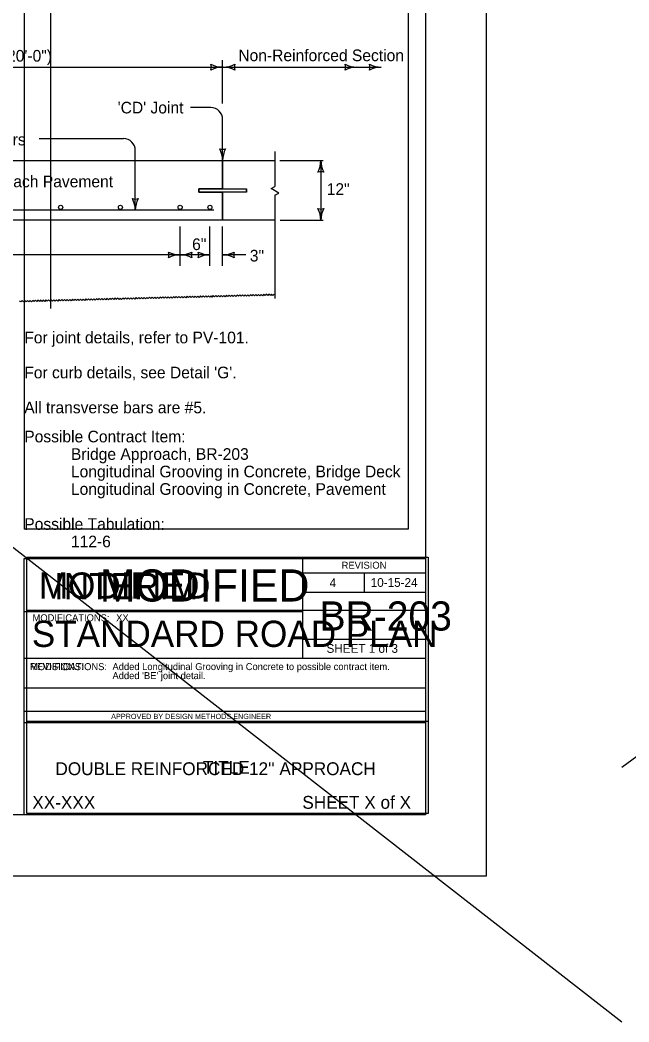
# Model space of a CAD drawing. Extents: x 8925 to 81668, y 4369 to 11918.
# Drawn here: x 12543 to 13587, y 4369 to 6087 of the extents above; entities that cross this region are included whole.
import ezdxf

# ---------------------------------------------------------------- set-up
doc = ezdxf.new("R2010")
doc.units = 0
for name, color, linetype in [('dsnCellElements', 7, 'Continuous'), ('dsnNonPlotable', 7, 'Continuous'), ('dsnShtPlotShapeBatchPrint', 7, 'Continuous'), ('dsnStdBlock', 7, 'Continuous'), ('dsnstdblockInterim', 7, 'Continuous'), ('dsnStdBlockModified', 7, 'Continuous'), ('dsnStdBlockNotModified', 7, 'Continuous'), ('dsnStdBorder', 7, 'Continuous'), ('dsnStdLabel', 7, 'Continuous'), ('dsnstdModifiedBlock', 7, 'Continuous'), ('Level 1', 7, 'Continuous'), ('Level 2', 7, 'Continuous'), ('Level 3', 7, 'Continuous'), ('SheetBorder', 7, 'Continuous')]:
    doc.layers.add(name, color=color, linetype=linetype)

msp = doc.modelspace()

# ---------------------------------------------------------------- linework, layer by layer
at = {"layer": 'dsnShtPlotShapeBatchPrint'}
for p, q in [((12890.1, 5943.6), (12890.1, 6018.3)), ((11921.5, 6006.2), (12890.1, 6006.2)), ((12890.1, 6006.1), (13161.7, 6006.1)), ((12869.9, 5936.8), (12835, 5936.8)), ((12890.1, 5846), (12890.1, 5916.6)), ((12575.6, 5883.6), (12720.2, 5883.6)), ((12740.4, 5760.8), (12740.4, 5863.4)), ((12433.4, 5846), (12890.1, 5846)), ((12433.4, 5846), (12890.1, 5846)), ((12890.1, 5846), (12890.1, 5797.7)), ((12890.1, 5846), (12979.6, 5846)), ((12988.4, 5845.9), (13062.2, 5845.9)), ((13058.4, 5845.9), (13058.4, 5743.6)), ((12890.1, 5797.7), (12849.2, 5797.7)), ((12849.2, 5797.7), (12849.2, 5792)), ((12849.2, 5797.7), (12849.2, 5792)), ((12849.2, 5792), (12890.1, 5792)), ((12890.1, 5792), (12890.1, 5743.7)), ((12931, 5792), (12931, 5797.7)), ((12890.1, 5743.7), (12433.4, 5743.7)), ((12890.1, 5743.7), (12433.4, 5743.7)), ((12979.6, 5743.7), (12890.1, 5743.7)), ((12988.9, 5743.6), (13062.2, 5743.6)), ((12817.2, 5665.2), (12817.2, 5733.2)), ((12868.3, 5665.2), (12868.3, 5733.2)), ((12890.1, 5665.2), (12890.1, 5733.2)), ((12817.2, 5684.2), (11994.4, 5684.2)), ((12868.3, 5684.2), (12817.2, 5684.2)), ((12929.9, 5684.2), (12890.1, 5684.2))]:
    msp.add_line(p, q, dxfattribs=at)
for points in [[(12542.9, 5604.6), (12541.8, 5605.7)], [(12597.6, 5606), (12596.4, 5607.1), (12594.2, 5604.8), (12591.8, 5607), (12589.6, 5604.7), (12587.3, 5606.9), (12585.1, 5604.5), (12582.7, 5606.8), (12580.5, 5604.4), (12578.2, 5606.6), (12576, 5604.3), (12573.6, 5606.5), (12571.4, 5604.2), (12569.1, 5606.4), (12566.9, 5604.1), (12564.5, 5606.3), (12562.3, 5604), (12560, 5606.2), (12557.8, 5603.8), (12555.4, 5606), (12553.2, 5603.7), (12550.9, 5605.9), (12548.7, 5603.6), (12546.3, 5605.8), (12544.1, 5603.5), (12542.9, 5604.6)], [(12652.2, 5607.4), (12651, 5608.5), (12648.8, 5606.2), (12646.4, 5608.4), (12644.2, 5606.1), (12641.9, 5608.3), (12639.7, 5606), (12637.3, 5608.2), (12635.1, 5605.9), (12632.8, 5608.1), (12630.6, 5605.7), (12628.2, 5607.9), (12626, 5605.6), (12623.7, 5607.8), (12621.5, 5605.5), (12619.1, 5607.7), (12616.9, 5605.4), (12614.6, 5607.6), (12612.4, 5605.3), (12610, 5607.5), (12607.8, 5605.1), (12605.5, 5607.3), (12603.3, 5605), (12600.9, 5607.2), (12598.7, 5604.9), (12597.6, 5606)], [(12706.8, 5608.9), (12705.6, 5610), (12703.4, 5607.6), (12701.1, 5609.8), (12698.8, 5607.5), (12696.5, 5609.7), (12694.3, 5607.4), (12691.9, 5609.6), (12689.7, 5607.3), (12687.4, 5609.5), (12685.2, 5607.2), (12682.9, 5609.4), (12680.6, 5607), (12678.3, 5609.3), (12676.1, 5606.9), (12673.8, 5609.1), (12671.5, 5606.8), (12669.2, 5609), (12667, 5606.7), (12664.6, 5608.9), (12662.4, 5606.6), (12660.1, 5608.8), (12657.9, 5606.4), (12655.5, 5608.7), (12653.3, 5606.3), (12652.2, 5607.4)], [(12761.4, 5610.3), (12760.2, 5611.4), (12758, 5609.1), (12755.7, 5611.3), (12753.4, 5608.9), (12751.1, 5611.2), (12748.9, 5608.8), (12746.6, 5611), (12744.3, 5608.7), (12742, 5610.9), (12739.8, 5608.6), (12737.5, 5610.8), (12735.2, 5608.5), (12732.9, 5610.7), (12730.7, 5608.3), (12728.4, 5610.6), (12726.1, 5608.2), (12723.8, 5610.4), (12721.6, 5608.1), (12719.3, 5610.3), (12717, 5608), (12714.7, 5610.2), (12712.5, 5607.9), (12710.2, 5610.1), (12707.9, 5607.8), (12706.8, 5608.9)], [(12816, 5611.7), (12814.8, 5612.8), (12812.6, 5610.5), (12810.3, 5612.7), (12808, 5610.4), (12805.7, 5612.6), (12803.5, 5610.3), (12801.2, 5612.5), (12798.9, 5610.1), (12796.6, 5612.3), (12794.4, 5610), (12792.1, 5612.2), (12789.9, 5609.9), (12787.5, 5612.1), (12785.3, 5609.8), (12783, 5612), (12780.7, 5609.7), (12778.4, 5611.9), (12776.2, 5609.5), (12773.9, 5611.7), (12771.6, 5609.4), (12769.3, 5611.6), (12767.1, 5609.3), (12764.8, 5611.5), (12762.5, 5609.2), (12761.4, 5610.3)], [(12871.6, 5613.1), (12870.4, 5614.2), (12868.2, 5611.9), (12865.8, 5614.1), (12863.6, 5611.8), (12861.3, 5614), (12859.1, 5611.7), (12856.7, 5613.9), (12854.5, 5611.6), (12852.2, 5613.8), (12850, 5611.4), (12847.6, 5613.7), (12845.4, 5611.3), (12843.1, 5613.5), (12840.9, 5611.2), (12838.5, 5613.4), (12836.3, 5611.1), (12834, 5613.3), (12831.8, 5611), (12829.4, 5613.2), (12827.2, 5610.8), (12824.9, 5613.1), (12822.7, 5610.7), (12820.3, 5612.9), (12818.1, 5610.6), (12816.9, 5611.7)], [(12925.2, 5614.6), (12924, 5615.7), (12921.8, 5613.3), (12919.5, 5615.6), (12917.3, 5613.2), (12914.9, 5615.4), (12912.7, 5613.1), (12910.4, 5615.3), (12908.2, 5613), (12905.8, 5615.2), (12903.6, 5612.9), (12901.3, 5615.1), (12899.1, 5612.7), (12896.7, 5615), (12894.5, 5612.6), (12892.2, 5614.8), (12890, 5612.5), (12887.6, 5614.7), (12885.4, 5612.4), (12883.1, 5614.6), (12880.9, 5612.3), (12878.5, 5614.5), (12876.3, 5612.2), (12874, 5614.4), (12871.8, 5612), (12870.6, 5613.1)], [(12979.8, 5616), (12978.6, 5617.1), (12976.4, 5614.8), (12974.1, 5617), (12971.9, 5614.6), (12969.5, 5616.9), (12967.3, 5614.5), (12965, 5616.7), (12962.8, 5614.4), (12960.4, 5616.6), (12958.2, 5614.3), (12955.9, 5616.5), (12953.7, 5614.2), (12951.3, 5616.4), (12949.1, 5614), (12946.8, 5616.3), (12944.6, 5613.9), (12942.2, 5616.1), (12940, 5613.8), (12937.7, 5616), (12935.5, 5613.7), (12933.1, 5615.9), (12930.9, 5613.6), (12928.6, 5615.8), (12926.4, 5613.5), (12925.2, 5614.6)]]:
    msp.add_lwpolyline(points, dxfattribs=at)
for centre in [(12869.9, 5916.6), (12720.2, 5863.4)]:
    msp.add_arc(centre, 20.2, 0, 90, dxfattribs=at)
at = {"layer": 'dsnStdBlock'}
msp.add_lwpolyline([(10103, 6733.9), (13238, 6733.9), (13238, 4723.9), (10103, 4723.9)], close=True, dxfattribs=at)
at = {"layer": 'dsnStdBlockModified'}
for p, q in [((12550, 6683.9), (12550, 5213.9)), ((13208, 6683.9), (13208, 5213.9)), ((12595, 6583.9), (12595, 5592.4)), ((13208, 5213.9), (12550, 5213.9))]:
    msp.add_line(p, q, dxfattribs=at)
at = {"layer": 'dsnStdBlockNotModified'}
msp.add_lwpolyline([(9998.5, 4619.4), (13342.5, 4619.4), (13342.5, 7203.4), (9998.5, 7203.4)], close=True, dxfattribs=at)
at = {"layer": 'dsnStdBorder'}
for p, q in [((12979.6, 5861.7), (12979.6, 5801.6)), ((12890.1, 5797.7), (12890.1, 5846)), ((12849.2, 5792), (12849.2, 5797.7)), ((12849.2, 5797.7), (12931, 5797.7)), ((12931, 5792), (12849.2, 5792)), ((12890.1, 5743.7), (12890.1, 5792)), ((12931, 5797.7), (12931, 5792)), ((12979.6, 5786.4), (12979.6, 5609.2)), ((12875, 5760.8), (12433.4, 5760.8))]:
    msp.add_line(p, q, dxfattribs=at)
msp.add_lwpolyline([(12979.6, 5786.4), (12986.2, 5790.2), (12973.1, 5797.8), (12979.6, 5801.6)], dxfattribs=at)
for centre, radius, start, end in [((12891.2, 6048.6), 42.5, 270, 298.0725), ((12891.2, 5963.6), 42.5, 61.9275, 90), ((12926.9, 6006.1), 16.4, 162.2666, 197.7334), ((13015.9, 5845.9), 42.5, 331.9275, 360), ((13015.9, 5845.9), 42.5, 331.9275, 360), ((13100.9, 5845.9), 42.5, 180, 208.0725), ((13100.9, 5845.9), 42.5, 180, 208.0725), ((13058.4, 5810.3), 16.4, 72.2666, 107.7334), ((13058.4, 5810.3), 16.4, 72.2666, 107.7334), ((13058.4, 5779.3), 16.4, 252.2666, 287.7333), ((13015.9, 5743.6), 42.5, 360, 28.0725), ((13100.9, 5743.6), 42.5, 151.9275, 180)]:
    msp.add_arc(centre, radius, start, end, dxfattribs=at)
at = {"layer": 'dsnstdModifiedBlock'}
for p, q in [((12554.3, 5074.8), (13242.3, 5074.8)), ((12554.3, 4884.8), (13242.3, 4884.8))]:
    msp.add_line(p, q, dxfattribs=at)
msp.add_lwpolyline([(12554.3, 5166.2), (13242.3, 5166.2), (13242.3, 4726.2), (12554.3, 4726.2)], close=True, dxfattribs=at)
at = {"layer": 'Level 1'}
for p, q in [((13027.1, 5163.9), (13027.1, 5072.6)), ((13027.1, 5139), (13238, 5139)), ((13132.6, 5139), (13132.6, 5105.8)), ((13027.1, 5105.8), (13238, 5105.8)), ((12550, 5072.6), (13027.1, 5072.6)), ((13027.1, 5072.6), (13027.1, 4992.6)), ((13238, 5024.8), (13027.1, 5024.8)), ((12550, 4992.6), (13238, 4992.6)), ((12550, 4941.6), (13238, 4941.6)), ((12550, 4901.6), (13238, 4901.6)), ((12550, 4882.6), (13238, 4882.6))]:
    msp.add_line(p, q, dxfattribs=at)
msp.add_lwpolyline([(12550, 5163.9), (13238, 5163.9), (13238, 4723.9), (12550, 4723.9)], close=True, dxfattribs=at)
at = {"layer": 'Level 2'}
for centre in [(12612.5, 5765.7), (12714.9, 5765.7), (12817.2, 5765.7), (12868.3, 5765.7)]:
    msp.add_circle(centre, 3.55, dxfattribs=at)
at = {"layer": 'Level 3'}
for centre, radius, start, end in [((12854.5, 6006.2), 16.4, 342.2666, 17.7333), ((12890.1, 6048.7), 42.5, 241.9275, 270), ((12890.1, 5963.7), 42.5, 90, 118.0725), ((13084.5, 6006.1), 16.4, 342.2666, 17.7333), ((13120.1, 6048.6), 42.5, 241.9275, 270), ((13120.1, 5963.6), 42.5, 90, 118.0725), ((13126, 6006.1), 16.4, 342.2666, 17.7333), ((13161.7, 6048.6), 42.5, 241.9275, 270), ((13161.7, 5963.6), 42.5, 90, 118.0725), ((12890.1, 5881.7), 16.4, 252.2666, 287.7333), ((12847.6, 5846), 42.5, 360, 28.0725), ((12932.6, 5846), 42.5, 151.9275, 180), ((12740.4, 5796.4), 16.4, 252.2666, 287.7333), ((12697.9, 5760.8), 42.5, 360, 28.0725), ((12782.9, 5760.8), 42.5, 151.9275, 180), ((12781.5, 5684.2), 16.4, 342.2666, 17.7333), ((12817.2, 5726.7), 42.5, 241.9275, 270), ((12817.2, 5726.7), 42.5, 270, 298.0725), ((12852.8, 5684.2), 16.4, 162.2666, 197.7334), ((12832.7, 5684.2), 16.4, 342.2666, 17.7333), ((12868.3, 5726.7), 42.5, 241.9275, 270), ((12890.1, 5726.7), 42.5, 270, 298.0725), ((12925.7, 5684.2), 16.4, 162.2666, 197.7334), ((12817.2, 5641.7), 42.5, 90, 118.0725), ((12817.2, 5641.7), 42.5, 61.9275, 90), ((12868.3, 5641.7), 42.5, 90, 118.0725), ((12890.1, 5641.7), 42.5, 61.9275, 90)]:
    msp.add_arc(centre, radius, start, end, dxfattribs=at)
at = {"layer": 'SheetBorder'}
for p, q in [((17092.5, 7422.9), (13574.6, 4805.2)), ((9795, 7316.3), (13574.6, 4369))]:
    msp.add_line(p, q, dxfattribs=at)

# ---------------------------------------------------------------- texts
at = {"layer": 'dsnCellElements'}
for s, height, p in [('MODIFIED', 45, (12575.1, 5094.7)), ('MODIFICATIONS:', 12, (12560, 4972.2))]:
    msp.add_text(s, height=height, dxfattribs=at).set_placement(p)
at = {"layer": 'dsnNonPlotable'}
msp.add_text('REVISIONS:', height=12, dxfattribs=at).set_placement((12560, 4972.2))
at = {"layer": 'dsnShtPlotShapeBatchPrint'}
for s, p in [('Single Reinforced Section (20\'-0")', (12196.5, 6015.6)), ('Non-Reinforced Section', (12917, 6016.4)), ("'CD' Joint", (12710.2, 5926.8)), ('#5 Bars At 12" Centers', (12279.9, 5872)), ('Approach Pavement', (12460, 5800.2)), ('12"', (13068.5, 5787.1)), ('6"', (12837.8, 5692.5)), ('3"', (12936.7, 5672.9))]:
    msp.add_text(s, height=20, dxfattribs=at).set_placement(p)
at = {"layer": 'dsnstdblockInterim'}
msp.add_text('INTERIM', height=45, dxfattribs=at).set_placement((12601, 5093.6))
at = {"layer": 'dsnStdLabel'}
for s, p in [('For joint details, refer to PV-101.', (12550.1, 5532.6)), ("For curb details, see Detail 'G'.", (12550.1, 5472.6)), ('All transverse bars are #5.', (12550.1, 5412.6)), ('Possible Contract Item:', (12550.1, 5362.8)), ('Bridge Approach, BR-203', (12630.1, 5332.8)), ('Longitudinal Grooving in Concrete, Bridge Deck', (12630.1, 5302.8)), ('Longitudinal Grooving in Concrete, Pavement', (12630.1, 5272.8)), ('Possible Tabulation:', (12550.1, 5212.8)), ('112-6', (12630.1, 5182.8))]:
    msp.add_text(s, height=20, dxfattribs=at).set_placement(p)
at = {"layer": 'dsnstdModifiedBlock'}
for s, height, p in [('MODIFIED', 55, (12679.4, 5089.9)), ('MODIFICATIONS:', 12, (12564.3, 5056)), ('XX', 12, (12707.6, 5056)), ('TITLE', 22, (12856.4, 4794.5)), ('XX-XXX', 22, (12563.9, 4734.5)), ('SHEET X of X', 22, (13026.7, 4734.5))]:
    msp.add_text(s, height=height, dxfattribs=at).set_placement(p)
at = {"layer": 'Level 1'}
for s, height, p in [('REVISION', 12, (13094.1, 5146.1)), ('4', 15, (13073.4, 5114.5)), ('10-15-24', 15, (13143.9, 5115)), ('BR-203', 50, (13056.3, 5040.1)), ('STANDARD ROAD PLAN', 45.001, (12563, 5012)), ('SHEET 1 of 3', 15, (13068.1, 5001.9)), ('Added Longitudinal Grooving in Concrete to possible contract item. ', 12, (12701.3, 4972.3)), ("Added 'BE' joint detail.", 12, (12701.3, 4956.8)), ('APPROVED BY DESIGN METHODS ENGINEER', 9.003, (12699, 4888.4)), ("DOUBLE REINFORCED 12'' APPROACH", 22, (12603.5, 4792.2))]:
    msp.add_text(s, height=height, dxfattribs=at).set_placement(p)

doc.saveas('drawing.dxf')
